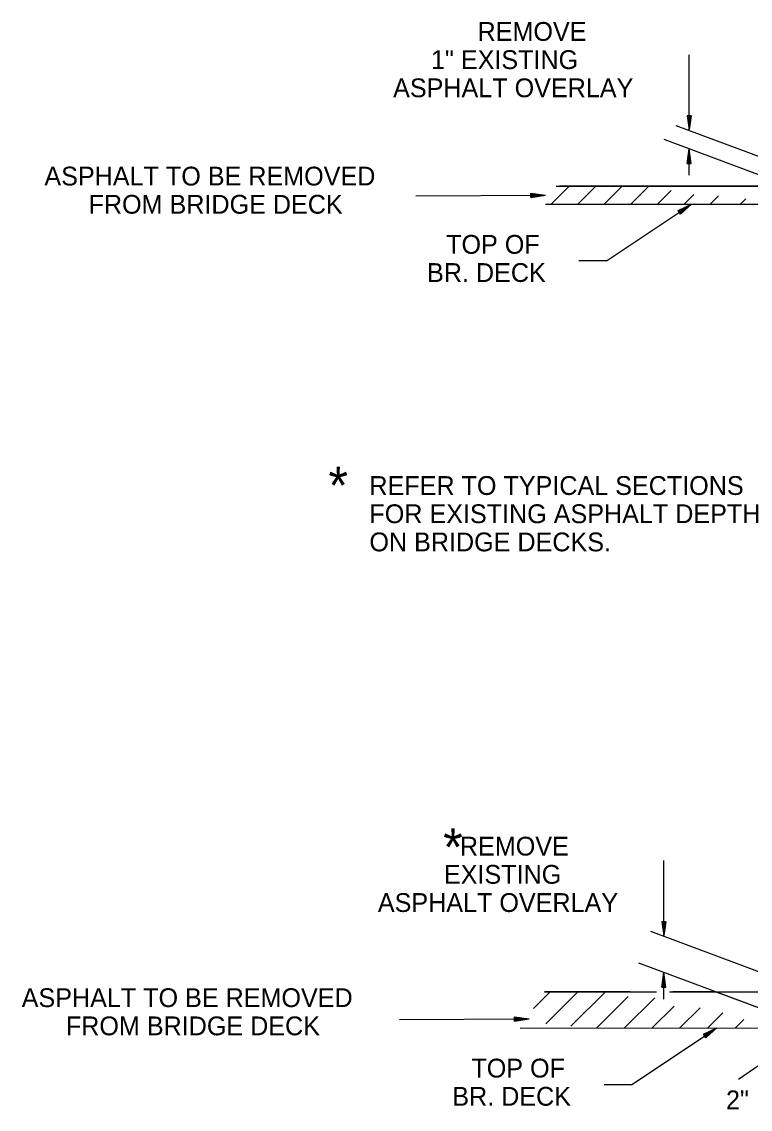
# Model space of a CAD drawing. Extents: x 1931522 to 1935523, y 600380 to 605075.
# Drawn here: x 1933030.7 to 1933263.2, y 602804.1 to 603151.2 of the extents above; entities that cross this region are included whole.
import ezdxf

# ---------------------------------------------------------------- set-up
doc = ezdxf.new("R2010")
doc.units = 0
doc.layers.add('Default', color=7, linetype='Continuous')
doc.layers.add('R_Border', color=7, linetype='Continuous')

msp = doc.modelspace()

# ---------------------------------------------------------------- linework, layer by layer
at = {"layer": 'Default'}
for p, q in [((1933243.76, 603116.66), (1933243.76, 603140.65)), ((1933243.09, 603121.11), (1933243.76, 603116.66)), ((1933243.09, 603121.11), (1933243.76, 603117.33)), ((1933244.42, 603121.11), (1933243.09, 603121.11)), ((1933243.32, 603121.11), (1933243.76, 603118.22)), ((1933243.32, 603121.11), (1933243.76, 603118.88)), ((1933243.54, 603121.11), (1933243.76, 603119.77)), ((1933243.54, 603121.11), (1933243.76, 603120.43)), ((1933244.42, 603121.11), (1933243.76, 603116.66)), ((1933243.97, 603121.11), (1933243.76, 603119.77)), ((1933244.2, 603121.11), (1933243.76, 603118.22)), ((1933244.2, 603121.11), (1933243.76, 603117.33)), ((1933243.97, 603121.11), (1933243.76, 603118.88)), ((1933243.76, 603121.11), (1933243.76, 603120.43)), ((1933291.14, 603098.73), (1933239.54, 603118)), ((1933291.14, 603092.96), (1933235.76, 603113.63)), ((1933243.09, 603105.97), (1933243.76, 603110.63)), ((1933243.09, 603105.97), (1933243.76, 603109.97)), ((1933243.32, 603105.97), (1933243.76, 603109.09)), ((1933243.32, 603105.97), (1933243.76, 603108.43)), ((1933244.42, 603105.97), (1933243.76, 603110.63)), ((1933243.76, 603102.2), (1933243.76, 603110.63)), ((1933244.2, 603105.97), (1933243.76, 603109.97)), ((1933244.2, 603105.97), (1933243.76, 603109.09)), ((1933243.97, 603105.97), (1933243.76, 603108.43)), ((1933243.09, 603105.97), (1933244.42, 603105.97)), ((1933243.54, 603105.97), (1933243.76, 603107.53)), ((1933243.54, 603105.97), (1933243.76, 603106.63)), ((1933243.97, 603105.97), (1933243.76, 603107.53)), ((1933243.76, 603105.97), (1933243.76, 603106.63)), ((1933199.65, 603092.95), (1933205.42, 603098.72)), ((1933201.32, 603098.72), (1933273.21, 603098.73)), ((1933208.14, 603092.95), (1933213.91, 603098.72)), ((1933216.62, 603092.96), (1933222.39, 603098.72)), ((1933225.11, 603092.96), (1933230.88, 603098.72)), ((1933156.43, 603095.68), (1933197.89, 603095.84)), ((1933193.18, 603095.12), (1933193.23, 603096.53)), ((1933193.18, 603096.22), (1933196.29, 603095.77)), ((1933193.18, 603095.12), (1933197.89, 603095.84)), ((1933193.23, 603096.53), (1933197.89, 603095.84)), ((1933193.23, 603095.43), (1933194.88, 603095.81)), ((1933193.23, 603095.43), (1933195.48, 603095.72)), ((1933193.28, 603095.73), (1933194.07, 603095.78)), ((1933193.28, 603095.73), (1933194.07, 603095.78)), ((1933193.32, 603096.04), (1933194.88, 603095.81)), ((1933193.32, 603096.04), (1933195.48, 603095.72)), ((1933193.36, 603096.35), (1933197.09, 603095.8)), ((1933193.36, 603095.25), (1933197.09, 603095.8)), ((1933193.36, 603095.25), (1933196.29, 603095.77)), ((1933233.6, 603092.96), (1933238.02, 603097.38)), ((1933242.08, 603092.96), (1933245.21, 603096.09)), ((1933250.43, 603092.96), (1933253.1, 603095.63)), ((1933260.1, 603092.96), (1933261.78, 603094.64)), ((1933197.89, 603092.95), (1933291.14, 603092.96)), ((1933217.31, 603074.84), (1933244.52, 603092.96)), ((1933240.24, 603090.96), (1933244.52, 603092.96)), ((1933240.98, 603089.76), (1933240.24, 603090.96)), ((1933240.37, 603090.68), (1933243.22, 603092.02)), ((1933240.45, 603090.89), (1933243.87, 603092.49)), ((1933240.59, 603090.61), (1933242.57, 603091.53)), ((1933240.59, 603090.61), (1933242.02, 603091.27)), ((1933240.73, 603090.33), (1933241.36, 603090.8)), ((1933240.73, 603090.33), (1933241.36, 603090.8)), ((1933240.85, 603090.04), (1933242.57, 603091.53)), ((1933240.85, 603090.04), (1933242.02, 603091.27)), ((1933240.98, 603089.76), (1933244.52, 603092.96)), ((1933241.06, 603089.97), (1933243.87, 603092.49)), ((1933241.06, 603089.97), (1933243.22, 603092.02)), ((1933217.31, 603074.84), (1933208.54, 603074.84)), ((1933235.66, 602859.5), (1933235.66, 602883.49)), ((1933234.99, 602863.95), (1933235.66, 602859.5)), ((1933234.99, 602863.95), (1933235.66, 602860.17)), ((1933236.32, 602863.95), (1933234.99, 602863.95)), ((1933235.22, 602863.95), (1933235.66, 602861.06)), ((1933235.22, 602863.95), (1933235.66, 602861.72)), ((1933235.43, 602863.95), (1933235.66, 602862.61)), ((1933235.43, 602863.95), (1933235.66, 602863.27)), ((1933236.32, 602863.95), (1933235.66, 602859.5)), ((1933235.87, 602863.95), (1933235.66, 602862.61)), ((1933236.1, 602863.95), (1933235.66, 602861.06)), ((1933236.1, 602863.95), (1933235.66, 602860.17)), ((1933235.87, 602863.95), (1933235.66, 602861.72)), ((1933235.66, 602863.95), (1933235.66, 602863.27)), ((1933283.04, 602841.57), (1933231.44, 602860.84)), ((1933283.04, 602830.03), (1933227.66, 602850.7)), ((1933234.99, 602843.04), (1933235.66, 602847.7)), ((1933236.32, 602843.04), (1933235.66, 602847.7)), ((1933235.66, 602839.27), (1933235.66, 602847.7)), ((1933234.99, 602843.04), (1933235.66, 602847.04)), ((1933235.22, 602843.04), (1933235.66, 602846.15)), ((1933235.22, 602843.04), (1933235.66, 602845.5)), ((1933235.43, 602843.04), (1933235.66, 602844.6)), ((1933236.1, 602843.04), (1933235.66, 602847.04)), ((1933236.1, 602843.04), (1933235.66, 602846.15)), ((1933235.87, 602843.04), (1933235.66, 602845.5)), ((1933235.87, 602843.04), (1933235.66, 602844.6)), ((1933194.02, 602836.28), (1933199.31, 602841.57)), ((1933197.59, 602841.57), (1933233.28, 602841.57)), ((1933197.97, 602831.4), (1933208.14, 602841.57)), ((1933206, 602830.58), (1933216.98, 602841.57)), ((1933234.99, 602843.04), (1933236.32, 602843.04)), ((1933235.43, 602843.04), (1933235.66, 602843.7)), ((1933235.66, 602843.04), (1933235.66, 602843.7)), ((1933237.48, 602841.57), (1933694.6, 602841.57)), ((1933214.28, 602830.03), (1933224.29, 602840.04)), ((1933223.12, 602830.03), (1933232.79, 602839.7)), ((1933231.96, 602830.03), (1933238.96, 602837.03)), ((1933240.8, 602830.03), (1933247.28, 602836.51)), ((1933249.64, 602830.03), (1933254.44, 602834.83)), ((1933151.22, 602832.75), (1933192.68, 602832.91)), ((1933187.96, 602832.19), (1933188.01, 602833.6)), ((1933187.96, 602832.19), (1933192.68, 602832.91)), ((1933187.97, 602833.29), (1933191.08, 602832.84)), ((1933188.01, 602833.6), (1933192.68, 602832.91)), ((1933188.02, 602832.49), (1933189.66, 602832.88)), ((1933188.02, 602832.49), (1933190.27, 602832.79)), ((1933188.06, 602832.8), (1933188.85, 602832.85)), ((1933188.06, 602832.8), (1933188.85, 602832.85)), ((1933188.11, 602833.11), (1933189.66, 602832.88)), ((1933188.11, 602833.11), (1933190.27, 602832.79)), ((1933188.14, 602833.42), (1933191.88, 602832.87)), ((1933188.14, 602832.32), (1933191.88, 602832.87)), ((1933188.14, 602832.32), (1933191.08, 602832.84)), ((1933258.48, 602830.03), (1933261.23, 602832.78)), ((1933189.79, 602830.02), (1933283.04, 602830.03)), ((1933225.37, 602811.92), (1933252.57, 602830.03)), ((1933248.3, 602828.03), (1933252.57, 602830.03)), ((1933249.04, 602826.83), (1933248.3, 602828.03)), ((1933248.43, 602827.76), (1933251.28, 602829.09)), ((1933248.5, 602827.96), (1933251.93, 602829.56)), ((1933248.65, 602827.68), (1933250.63, 602828.61)), ((1933248.65, 602827.68), (1933250.07, 602828.35)), ((1933248.78, 602827.4), (1933249.41, 602827.87)), ((1933248.78, 602827.4), (1933249.41, 602827.87)), ((1933248.91, 602827.12), (1933250.63, 602828.61)), ((1933248.91, 602827.12), (1933250.07, 602828.35)), ((1933249.04, 602826.83), (1933252.57, 602830.03)), ((1933249.11, 602827.05), (1933251.93, 602829.56)), ((1933249.11, 602827.05), (1933251.28, 602829.09)), ((1933259.48, 602813.73), (1933283.04, 602830.03)), ((1933225.37, 602811.92), (1933216.59, 602811.92))]:
    msp.add_line(p, q, dxfattribs=at)
for points in [[(1933197.89, 603092.95), (1933291.14, 603092.96), (1933275.7, 603098.73)], [(1933273.32, 603098.73), (1933202.31, 603098.72)], [(1933224.86, 602841.57), (1933197.59, 602841.57)], [(1933283.04, 602830.03), (1933252.13, 602841.57), (1933238.5, 602841.57)]]:
    msp.add_lwpolyline(points, dxfattribs=at)

# ---------------------------------------------------------------- texts
for s, p in [('REMOVE', (1933176.18, 603145.1)), ('1" EXISTING ', (1933161.3, 603136.1)), ('ASPHALT OVERLAY', (1933149.21, 603127.1)), ('ASPHALT TO BE REMOVED', (1933037.89, 603098.93)), (' FROM BRIDGE DECK', (1933049.76, 603089.93)), ('TOP OF ', (1933166.15, 603077.14)), ('BR. DECK', (1933160.05, 603068.14)), (' REMOVE', (1933168.31, 602885.06)), ('EXISTING ', (1933165.44, 602876.06)), ('ASPHALT OVERLAY', (1933144.34, 602867.06)), ('ASPHALT TO BE REMOVED', (1933030.64, 602836.7)), (' FROM BRIDGE DECK', (1933042.51, 602827.7)), ('TOP OF ', (1933174.21, 602814.22)), ('BR. DECK', (1933168.11, 602805.22)), ('2"', (1933255.49, 602804.09))]:
    msp.add_text(s, height=6, rotation=360, dxfattribs=at).set_placement(p)
at = {"layer": 'R_Border'}
for s, height, p in [('*', 12, (1933128.56, 602997.22)), ('REFER TO TYPICAL SECTIONS', 6, (1933141.65, 603000.16)), ('FOR EXISTING ASPHALT DEPTH ', 6, (1933141.65, 602991.16)), ('ON BRIDGE DECKS.', 6, (1933141.65, 602982.16)), ('*', 12, (1933165.2, 602881.77))]:
    msp.add_text(s, height=height, rotation=360, dxfattribs=at).set_placement(p)

doc.saveas('drawing.dxf')
